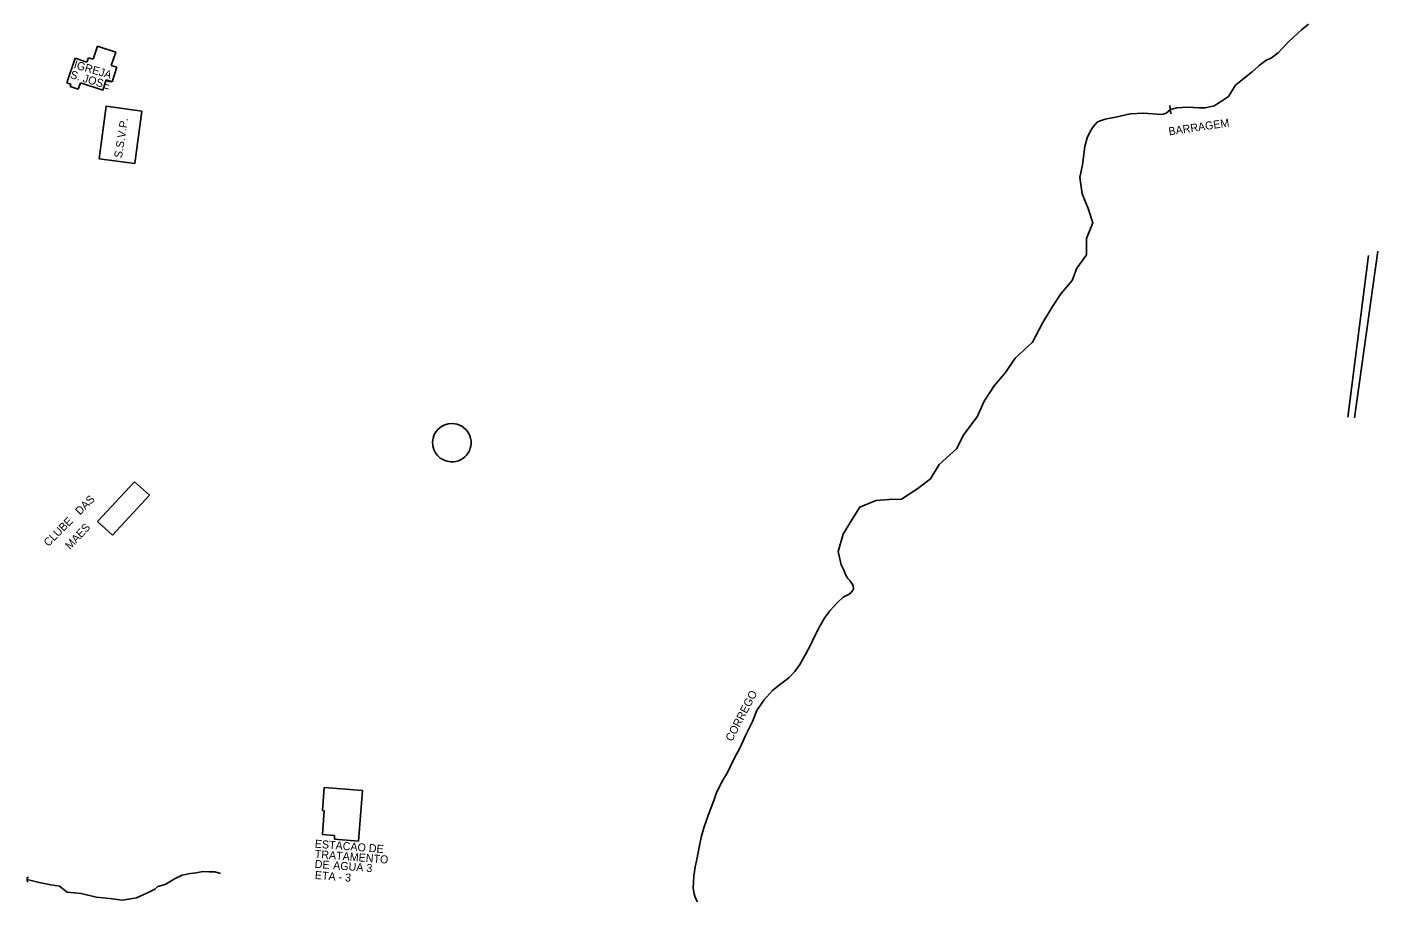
# Model space of a CAD drawing. Extents: x 325899 to 364828, y 7568995 to 7592502.
# Drawn here: x 337914 to 338590, y 7587341 to 7587778 of the extents above; entities that cross this region are included whole.
import ezdxf

# ---------------------------------------------------------------- set-up
doc = ezdxf.new("R2010")
doc.units = 0
for name, color, linetype in [('EDIFEXISTENT', 7, 'Continuous'), ('EDIFIDENTIF', 7, 'Continuous'), ('EDIFOBRAEXIS', 7, 'Continuous')]:
    doc.layers.add(name, color=color, linetype=linetype)

msp = doc.modelspace()

# ---------------------------------------------------------------- linework, layer by layer
at = {"layer": 'EDIFEXISTENT'}
for p, q in [((337947.25, 7587761.42), (337949.43, 7587768.03)), ((337949.43, 7587768.03), (337958.58, 7587765.02)), ((337934.21, 7587749.6), (337938.27, 7587761.91)), ((337938.27, 7587761.91), (337944.21, 7587759.95)), ((337944.21, 7587759.95), (337944.94, 7587762.18)), ((337944.94, 7587762.18), (337947.25, 7587761.42)), ((337958.58, 7587765.02), (337956.39, 7587758.39)), ((337956.39, 7587758.39), (337959.18, 7587757.47)), ((337959.18, 7587757.47), (337956.76, 7587750.15)), ((337936.13, 7587749.01), (337934.21, 7587749.6)), ((337935.75, 7587747.87), (337936.13, 7587749.01)), ((337939.88, 7587746.51), (337935.75, 7587747.87)), ((337940.91, 7587749.62), (337939.88, 7587746.51)), ((337952.15, 7587745.92), (337940.91, 7587749.62)), ((337953.86, 7587751.1), (337952.15, 7587745.92)), ((337956.76, 7587750.15), (337953.86, 7587751.1)), ((337950.36, 7587711.72), (337953.9, 7587737.92)), ((337953.9, 7587737.92), (337971.69, 7587735.53)), ((337971.69, 7587735.53), (337968.16, 7587709.32)), ((338486.02, 7587734.14), (338485.44, 7587738.28)), ((337968.16, 7587709.32), (337950.36, 7587711.72)), ((337949.57, 7587530.3), (337967.94, 7587550.17)), ((337967.94, 7587550.17), (337975.54, 7587543.47)), ((337975.54, 7587543.47), (337957.01, 7587523.56)), ((337957.01, 7587523.56), (337949.57, 7587530.3)), ((338062.03, 7587385.8), (338062.81, 7587397.31)), ((338062.81, 7587397.31), (338081.9, 7587395.79)), ((338081.9, 7587395.79), (338079.89, 7587370.55)), ((338061.9, 7587373.77), (338062.85, 7587385.74)), ((338062.85, 7587385.74), (338062.03, 7587385.8)), ((338068.02, 7587373.29), (338061.9, 7587373.77)), ((338067.88, 7587371.5), (338068.02, 7587373.29)), ((338079.89, 7587370.55), (338067.88, 7587371.5)), ((337914.26, 7587350.58), (337914.32, 7587351.33)), ((337914.76, 7587350.15), (337914.26, 7587350.58)), ((337914.28, 7587352.26), (337914.93, 7587352.56)), ((337914.32, 7587351.33), (337914.28, 7587352.26))]:
    msp.add_line(p, q, dxfattribs=at)
at = {"layer": 'EDIFOBRAEXIS'}
for points in [[(338481.39, 7587733.87), (338482.24, 7587733.97), (338483.71, 7587734.54), (338485.81, 7587736.33), (338489.08, 7587737.18), (338491.69, 7587737.38), (338494.71, 7587737.42), (338499.96, 7587737.1), (338503.15, 7587737.17), (338507.66, 7587738.21), (338510.87, 7587740.13), (338514.76, 7587742.9), (338518.3, 7587748.45), (338522.62, 7587751.98), (338526.65, 7587755.2), (338529.53, 7587757.62), (338530.16, 7587758.39), (338533.42, 7587760.74), (338536.3, 7587762.18), (338539.66, 7587764.61), (338541.88, 7587766.91), (338545.05, 7587770.25), (338551.28, 7587776.1), (338554.84, 7587779.01)], [(338324.57, 7587501.91), (338324.57, 7587501.91), (338324.57, 7587501.91), (338324.57, 7587501.91), (338323.5, 7587503.46), (338322.53, 7587506), (338321.26, 7587508.66), (338321.26, 7587508.66), (338321.26, 7587508.66), (338319.72, 7587515.35), (338319.72, 7587515.35), (338322.3, 7587523.97), (338322.3, 7587523.97), (338322.3, 7587523.97), (338326.08, 7587530.29), (338326.08, 7587530.29), (338326.08, 7587530.29), (338330.58, 7587537.57), (338330.58, 7587537.57), (338330.58, 7587537.57), (338338.54, 7587540.91), (338338.54, 7587540.91), (338345.18, 7587541.27), (338345.18, 7587541.27), (338351.44, 7587541.42), (338351.44, 7587541.42), (338351.44, 7587541.42), (338359.58, 7587546.79), (338359.58, 7587546.79), (338365.86, 7587551.71), (338365.86, 7587551.71), (338370.18, 7587558.87), (338370.18, 7587558.87), (338370.18, 7587558.87), (338378.84, 7587566.67), (338382.48, 7587573.77), (338382.48, 7587573.77), (338382.48, 7587573.77), (338389.23, 7587582.63), (338389.23, 7587582.63), (338389.23, 7587582.63), (338392.74, 7587590.44), (338392.74, 7587590.44), (338392.74, 7587590.44), (338397.77, 7587598.19), (338397.77, 7587598.19), (338397.77, 7587598.19), (338403.4, 7587604.9), (338403.4, 7587604.9), (338408.18, 7587612.01), (338408.18, 7587612.01), (338408.18, 7587612.01), (338416.81, 7587620.02), (338416.54, 7587619.77), (338416.81, 7587620.02), (338422.05, 7587629.75), (338422.05, 7587629.75), (338422.05, 7587629.75), (338426.78, 7587637.9), (338426.78, 7587637.9), (338431.06, 7587644.15), (338431.06, 7587644.15), (338431.06, 7587644.15), (338436.66, 7587650.76), (338436.66, 7587650.76), (338436.66, 7587650.76), (338439.07, 7587657.02), (338439.07, 7587657.02), (338443.91, 7587663.67), (338443.91, 7587663.67), (338443.91, 7587663.67), (338443.84, 7587671.84), (338443.84, 7587671.84), (338443.84, 7587671.84), (338446.94, 7587679.67), (338446.94, 7587679.67), (338446.94, 7587679.67), (338446.94, 7587679.67), (338444.73, 7587686.85), (338444.73, 7587686.85), (338444.73, 7587686.85), (338444.73, 7587686.85), (338444.73, 7587686.85), (338441.63, 7587694.13), (338441.63, 7587694.13), (338441.63, 7587694.13), (338440.47, 7587702.38), (338440.47, 7587702.38), (338441.94, 7587708.63), (338441.94, 7587708.63), (338442.98, 7587717.87), (338444.21, 7587722.16), (338445.68, 7587725.32), (338447.11, 7587727.69), (338449.42, 7587730.17), (338453.24, 7587731.44), (338459.13, 7587732.63), (338459.13, 7587732.63), (338465.76, 7587734.1), (338465.76, 7587734.1), (338465.76, 7587734.1), (338465.76, 7587734.1), (338472.5, 7587734.49), (338472.5, 7587734.49), (338481.39, 7587733.87), (338480.26, 7587733.95)], [(338584.83, 7587663.28), (338574.45, 7587582.58)], [(338589.56, 7587665.45), (338577.85, 7587582.18)], [(338324.57, 7587501.91), (338325.59, 7587500.82), (338327.23, 7587498.36), (338327.41, 7587496.55), (338326.2, 7587494.83), (338325.2, 7587494.07), (338322.2, 7587492.5), (338319.43, 7587489.92), (338315.57, 7587485.66), (338313.01, 7587482.34), (338310.51, 7587478.01), (338307.67, 7587472.53), (338306.11, 7587468.86), (338303.57, 7587464.17), (338300.57, 7587458.8), (338298.01, 7587455.32), (338295.01, 7587452.16), (338290.44, 7587448.61), (338286.96, 7587445.83), (338282.49, 7587441.04), (338279.11, 7587435.79), (338276.92, 7587430.29), (338273.69, 7587424.03), (338270.54, 7587416.93), (338267.79, 7587411.79), (338264.33, 7587404.89), (338261.51, 7587400.18), (338258.74, 7587394.27), (338257.6, 7587390.9), (338254.87, 7587383.83), (338252.51, 7587377.26), (338251.23, 7587372.34), (338250.46, 7587368.33), (338249.04, 7587361.41), (338248.22, 7587357.63), (338247.63, 7587352.97), (338247.32, 7587347.08), (338247.69, 7587344.17), (338248.23, 7587342.39), (338249.34, 7587340.18)], [(337914.36, 7587351.41), (337920.25, 7587349.91), (337926.13, 7587348.66), (337930.5, 7587348.04), (337934.32, 7587345.07), (337941.27, 7587344.33), (337948.88, 7587342.44), (337955.55, 7587341.77), (337961.91, 7587341.03), (337968.92, 7587342.16), (337974.12, 7587344.44), (337978.2, 7587346.49), (337979.7, 7587347.91), (337983.23, 7587348.89), (337988.36, 7587351.9), (337991.76, 7587353.57), (337995.84, 7587354.3), (337998.78, 7587354.68), (338002.08, 7587355.28), (338005.25, 7587355.15), (338008.22, 7587355.2), (338011.01, 7587354.36)]]:
    msp.add_lwpolyline(points, dxfattribs=at)
for centre, start, end in [((338126.52, 7587569.76), 88.57247, 267.40721), ((338126.69, 7587569.75), 266.36797, 89.61171)]:
    msp.add_arc(centre, 9.57, start, end, dxfattribs=at)

# ---------------------------------------------------------------- texts
at = {"layer": 'EDIFIDENTIF'}
for s, rotation, p in [('IGREJA', 343.47895, (337937.34, 7587757.1)), ('S. JOSE', 343.34372, (337935.56, 7587752.12)), ('S.S.V.P.', 80.9264, (337961.67, 7587711.86)), ('BARRAGEM', 8.49021, (338485.18, 7587723.36)), ('CLUBE   DAS', 45.04548, (337924.95, 7587517.54)), ('MAES', 46.84531, (337935.81, 7587516.05)), ('CORREGO', 62.5004, (338266.69, 7587420.05)), ('ESTACAO DE', 355.44702, (338058, 7587367.3)), ('TRATAMENTO', 355.44702, (338057.98, 7587362.19)), ('DE', 355.44702, (338057.94, 7587357.22)), ('ETA - 3', 355.44702, (338058.01, 7587351.63)), ('AGUA 3', 355.44702, (338067.16, 7587356.54))]:
    msp.add_text(s, height=4, rotation=rotation, dxfattribs=at).set_placement(p)

doc.saveas('drawing.dxf')
